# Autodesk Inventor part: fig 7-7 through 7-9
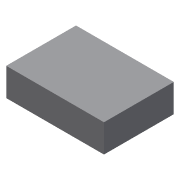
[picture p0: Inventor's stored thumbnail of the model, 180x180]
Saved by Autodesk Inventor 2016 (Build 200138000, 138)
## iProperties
Created: 2009-09
Part Number: fig 7-7 through 7-9
Document SubType Name: Modeling
Designer: Sham
Density: 1 g/cm^3
Material: Generic
Appearance: Default
Author: Sham
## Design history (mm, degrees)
sketch "Sketch1"
  geometry: L1 (-28, 20)-(0, 20); L2 (0, 20)-(0, 0); L3 (0, 0)-(-28, 0); L4 (-28, 0)-(-28, 20)
  constraints: 8 end point, 2 parallel, 1 horizontal, 1 perpendicular
extrude "Extrusion1" new body sketch "Sketch1" distance "d0" = 8; taper "d1" = 0 deg
body "Solid1"
